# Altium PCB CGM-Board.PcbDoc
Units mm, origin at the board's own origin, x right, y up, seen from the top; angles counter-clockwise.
Board outline 25 x 32 mm, 4 copper layers (Top Layer, Signal Layer 2, Signal Layer 3, Bottom Layer), stack 1.6 mm thick; 78 components, 47 nets, 236 pads, 227 vias.
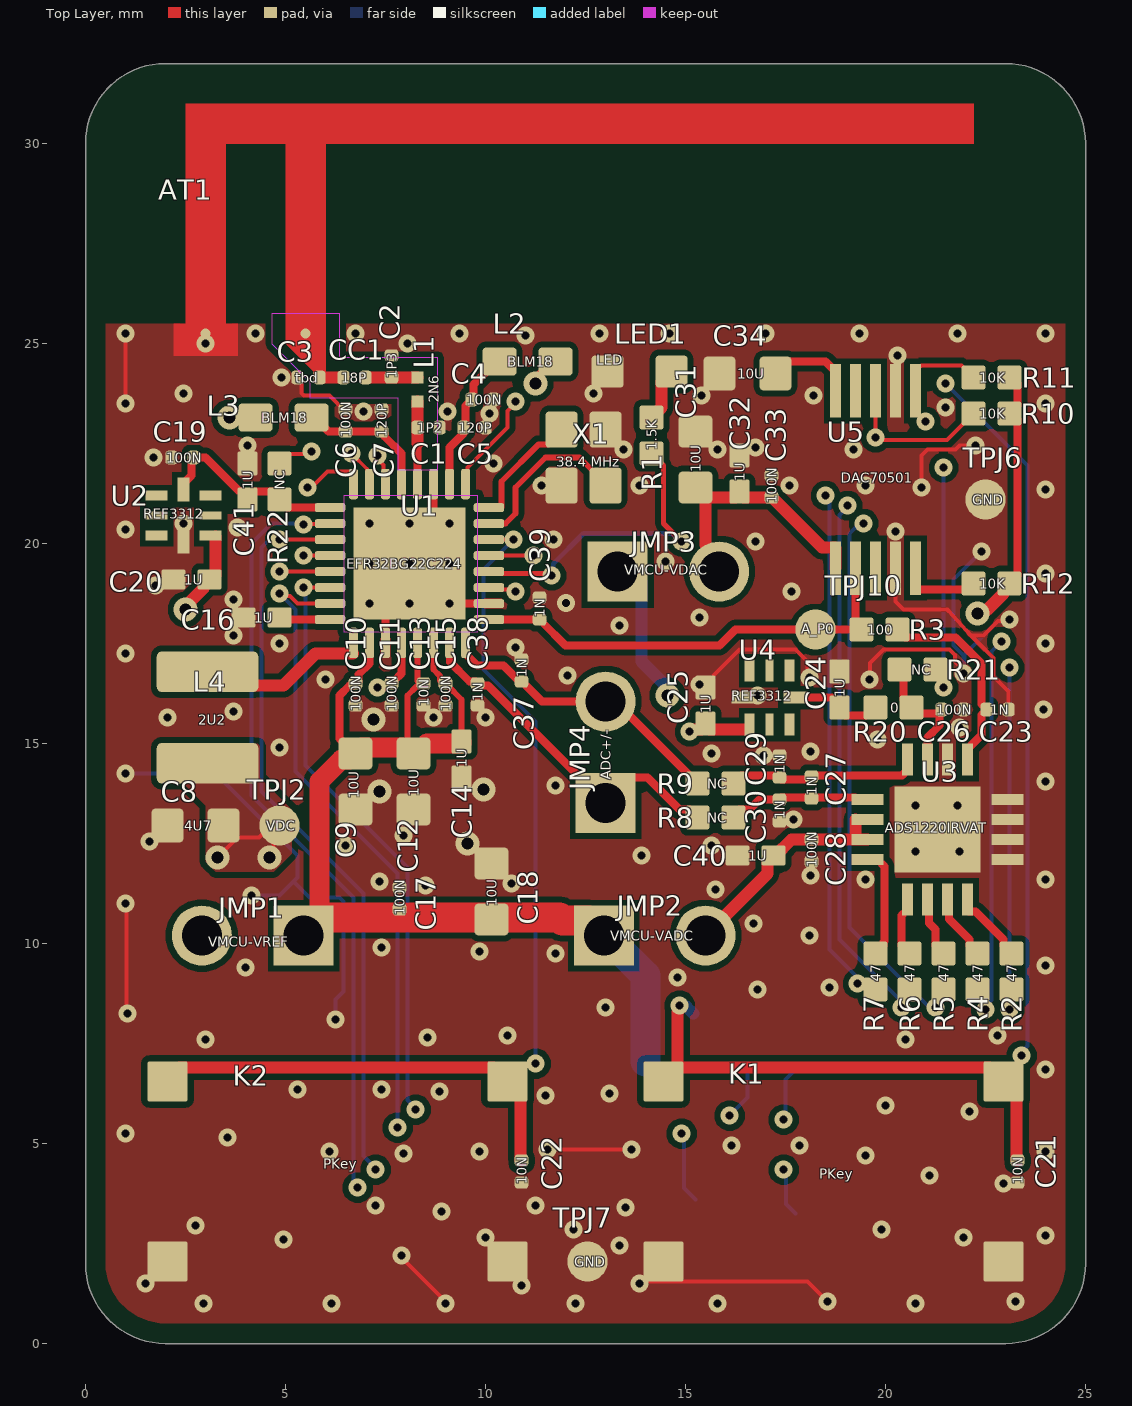
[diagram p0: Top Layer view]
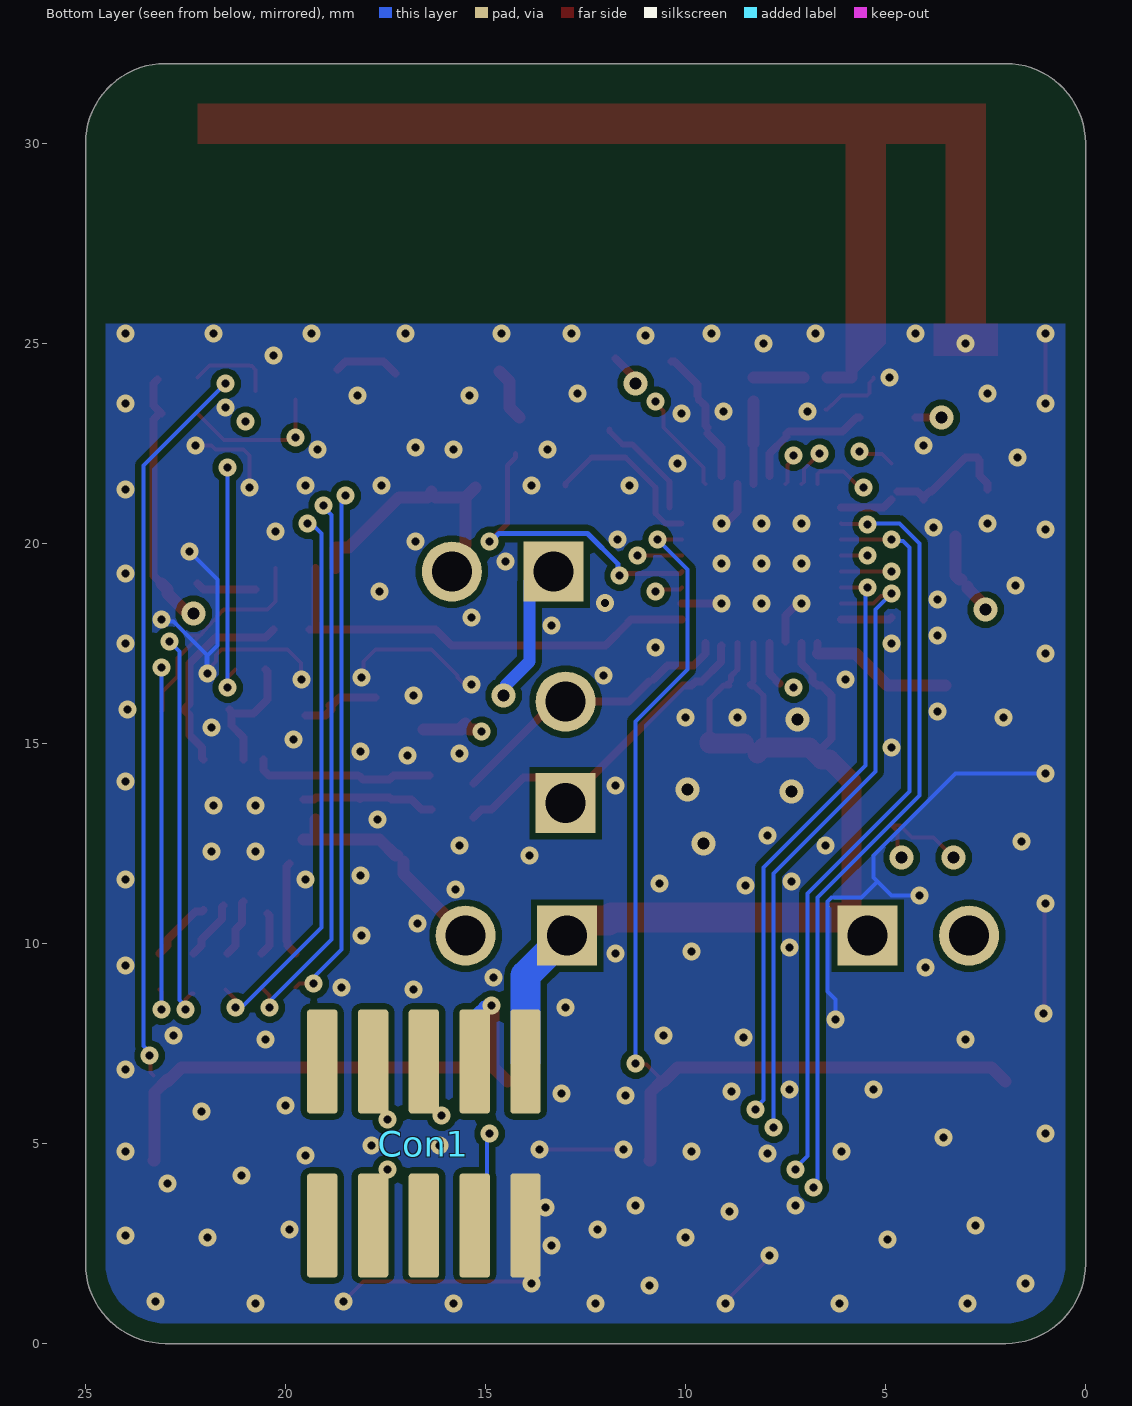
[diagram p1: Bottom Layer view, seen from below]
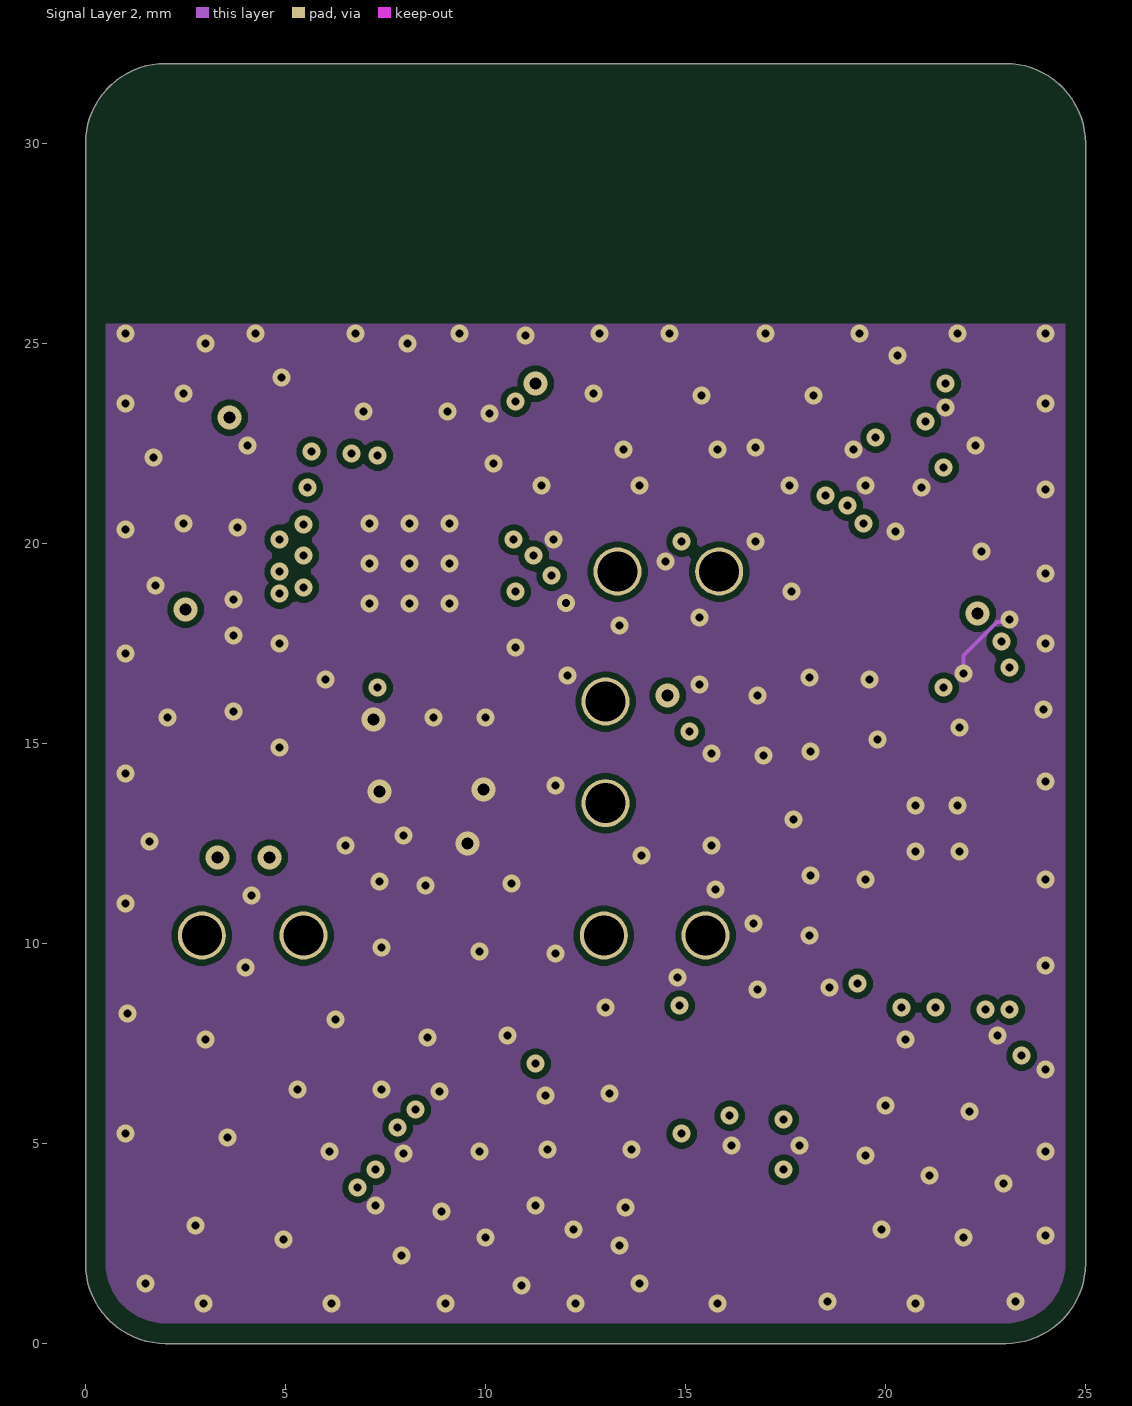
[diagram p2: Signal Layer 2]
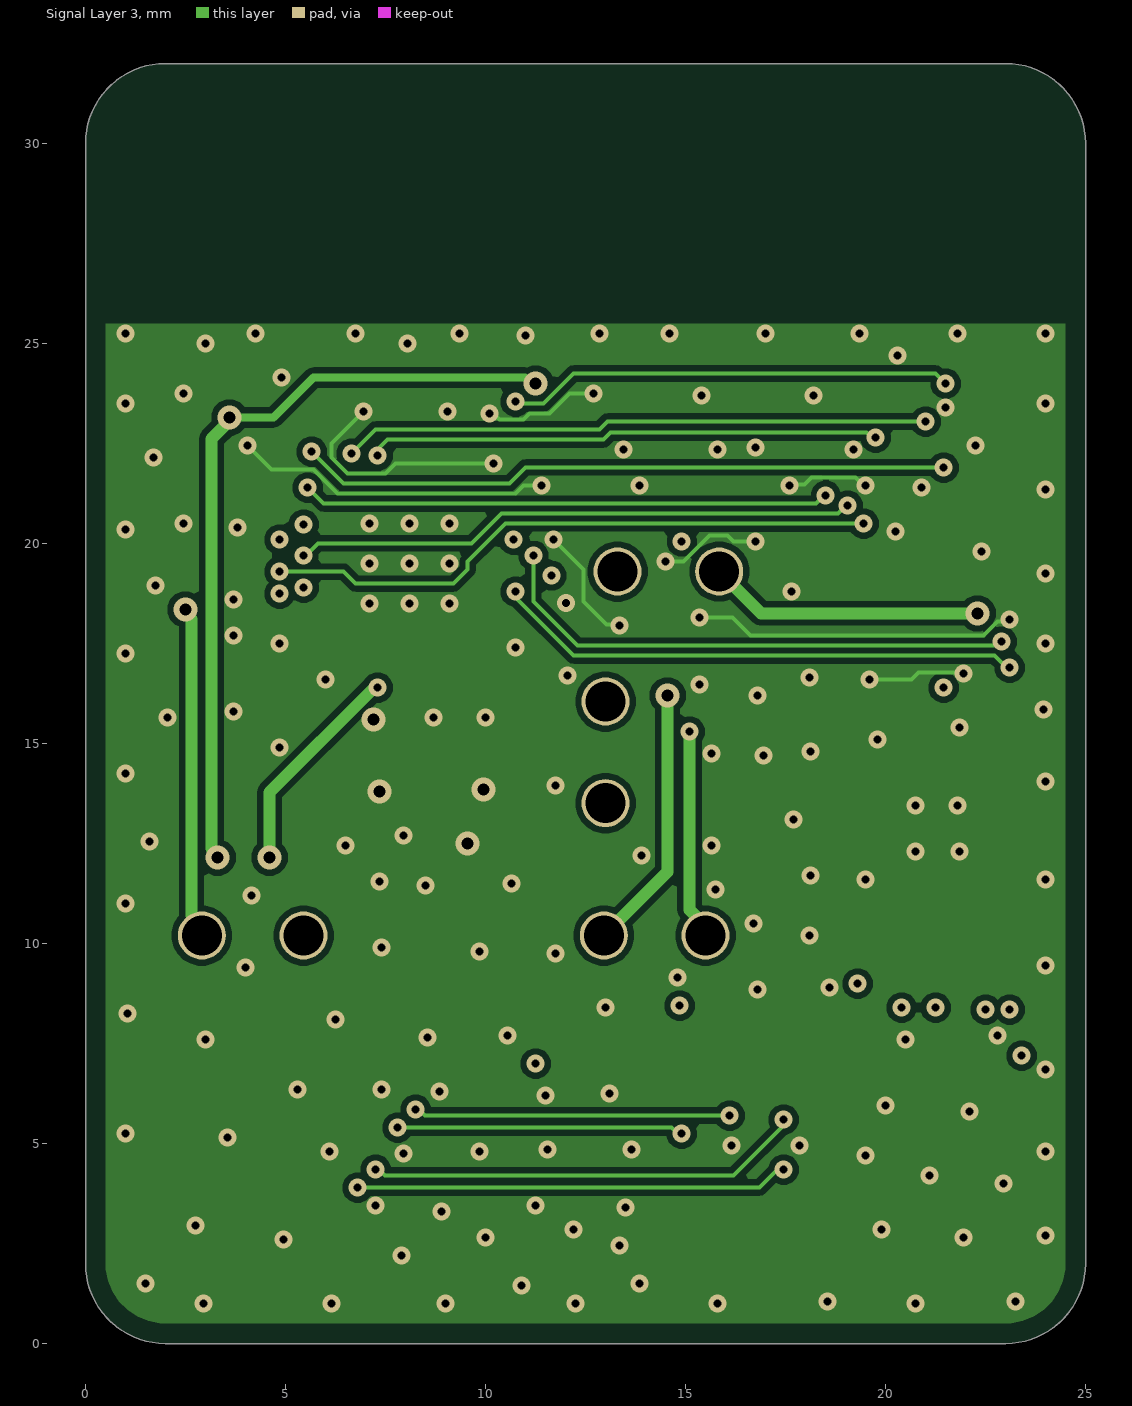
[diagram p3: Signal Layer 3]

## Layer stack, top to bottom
Top Solder: solder mask 0.0102, Solder Resist, Dk 3.5
Top Layer: signal copper 0.035
Dielectric 1: core 0.325, FR-4, Dk 4.2
Signal Layer 2: signal copper 0.018
Dielectric 3: prepreg 0.844, Dk 4.2
Signal Layer 3: signal copper 0.018
Dielectric 2: core 0.325, Dk 4.2
Bottom Layer: signal copper 0.035
Bottom Solder: solder mask 0.0102, Solder Resist, Dk 3.5

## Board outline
0,2 0,30 cw(c2,30) 2,32 23,32 cw(c23,30) 25,30 25,2 cw(c23,2) 23,0 2,0 cw(c2,2)

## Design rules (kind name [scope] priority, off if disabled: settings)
AcuteAngle [All] p1: minimum=7.00000000000000E+0001 checktracksonly=FALSE
BoardOutlineClearance [All] p1: gap=0.5 ignorepadtopadclearanceinfootprint=FALSE
Clearance Clearance_General [All] p1: gap=0.1 ignorepadtopadclearanceinfootprint=FALSE except(0.15: Arc-Poly Track-Poly SMDPad-Poly THPad-Poly Via-Poly Fill-Poly Poly-Poly Poly-Region Poly-Text Poly-Hole)
Clearance Clearance_RF [InNetClass('RF-Traces') vs InNet('GND')] p2: gap=0.5 ignorepadtopadclearanceinfootprint=FALSE
DiffPairsRouting [All] p1: maxlimit=0.254 minlimit=0.254 mostfreqgap=0.254 toplayer_minwidth=0.381 toplayer_maxwidth=0.381 toplayer_prefwidth=0.381 midlayer1_minwidth=0.381 midlayer1_maxwidth=0.381 midlayer1_prefwidth=0.381 midlayer2_minwidth=0.381 midlayer2_maxwidth=0.381 midlayer2_prefwidth=0.381 bottomlayer_minwidth=0.381 bottomlayer_maxwidth=0.381 bottomlayer_prefwidth=0.381 substack1={FA8A8519-551F-42C4-AF21-50C5882F2CE8} toplayer_{fa8a8519-551f-42c4-af21-50c5882f2ce8}_minwidth=0.381 toplayer_{fa8a8519-551f-42c4-af21-50c5882f2ce8}_maxwidth=0.381 toplayer_{fa8a8519-551f-42c4-af21-50c5882f2ce8}_prefwidth=0.381 midlayer1_{fa8a8519-551f-42c4-af21-50c5882f2ce8}_minwidth=0.381 midlayer1_{fa8a8519-551f-42c4-af21-50c5882f2ce8}_maxwidth=0.381 midlayer1_{fa8a8519-551f-42c4-af21-50c5882f2ce8}_prefwidth=0.381 midlayer2_{fa8a8519-551f-42c4-af21-50c5882f2ce8}_minwidth=0.381 midlayer2_{fa8a8519-551f-42c4-af21-50c5882f2ce8}_maxwidth=0.381 midlayer2_{fa8a8519-551f-42c4-af21-50c5882f2ce8}_prefwidth=0.381 bottomlayer_{fa8a8519-551f-42c4-af21-50c5882f2ce8}_minwidth=0.381 bottomlayer_{fa8a8519-551f-42c4-af21-50c5882f2ce8}_maxwidth=0.381 bottomlayer_{fa8a8519-551f-42c4-af21-50c5882f2ce8}_prefwidth=0.381 substack2={B08C36B3-7862-438E-B9FF-C3538867186E} toplayer_{b08c36b3-7862-438e-b9ff-c3538867186e}_minwidth=0.381 toplayer_{b08c36b3-7862-438e-b9ff-c3538867186e}_maxwidth=0.381 toplayer_{b08c36b3-7862-438e-b9ff-c3538867186e}_prefwidth=0.381 midlayer1_{b08c36b3-7862-438e-b9ff-c3538867186e}_minwidth=0.381 midlayer1_{b08c36b3-7862-438e-b9ff-c3538867186e}_maxwidth=0.381 midlayer1_{b08c36b3-7862-438e-b9ff-c3538867186e}_prefwidth=0.381 midlayer2_{b08c36b3-7862-438e-b9ff-c3538867186e}_minwidth=0.381 midlayer2_{b08c36b3-7862-438e-b9ff-c3538867186e}_maxwidth=0.381 midlayer2_{b08c36b3-7862-438e-b9ff-c3538867186e}_prefwidth=0.381 bottomlayer_{b08c36b3-7862-438e-b9ff-c3538867186e}_minwidth=0.381 bottomlayer_{b08c36b3-7862-438e-b9ff-c3538867186e}_maxwidth=0.381 bottomlayer_{b08c36b3-7862-438e-b9ff-c3538867186e}_prefwidth=0.381 substack3={B8B36AB3-2B2C-415E-8633-38694F6D9F5F} toplayer_{b8b36ab3-2b2c-415e-8633-38694f6d9f5f}_minwidth=0.381 toplayer_{b8b36ab3-2b2c-415e-8633-38694f6d9f5f}_maxwidth=0.381 toplayer_{b8b36ab3-2b2c-415e-8633-38694f6d9f5f}_prefwidth=0.381 midlayer1_{b8b36ab3-2b2c-415e-8633-38694f6d9f5f}_minwidth=0.381 midlayer1_{b8b36ab3-2b2c-415e-8633-38694f6d9f5f}_maxwidth=0.381 midlayer1_{b8b36ab3-2b2c-415e-8633-38694f6d9f5f}_prefwidth=0.381 midlayer2_{b8b36ab3-2b2c-415e-8633-38694f6d9f5f}_minwidth=0.381 midlayer2_{b8b36ab3-2b2c-415e-8633-38694f6d9f5f}_maxwidth=0.381 midlayer2_{b8b36ab3-2b2c-415e-8633-38694f6d9f5f}_prefwidth=0.381 bottomlayer_{b8b36ab3-2b2c-415e-8633-38694f6d9f5f}_minwidth=0.381 bottomlayer_{b8b36ab3-2b2c-415e-8633-38694f6d9f5f}_maxwidth=0.381 bottomlayer_{b8b36ab3-2b2c-415e-8633-38694f6d9f5f}_prefwidth=0.381 substack4={C90E24FC-0848-4387-93FF-582D14C2B24E} toplayer_{c90e24fc-0848-4387-93ff-582d14c2b24e}_minwidth=0.381 toplayer_{c90e24fc-0848-4387-93ff-582d14c2b24e}_maxwidth=0.381 toplayer_{c90e24fc-0848-4387-93ff-582d14c2b24e}_prefwidth=0.381 midlayer1_{c90e24fc-0848-4387-93ff-582d14c2b24e}_minwidth=0.381 midlayer1_{c90e24fc-0848-4387-93ff-582d14c2b24e}_maxwidth=0.381 midlayer1_{c90e24fc-0848-4387-93ff-582d14c2b24e}_prefwidth=0.381 midlayer2_{c90e24fc-0848-4387-93ff-582d14c2b24e}_minwidth=0.381 midlayer2_{c90e24fc-0848-4387-93ff-582d14c2b24e}_maxwidth=0.381 midlayer2_{c90e24fc-0848-4387-93ff-582d14c2b24e}_prefwidth=0.381 bottomlayer_{c90e24fc-0848-4387-93ff-582d14c2b24e}_minwidth=0.381 bottomlayer_{c90e24fc-0848-4387-93ff-582d14c2b24e}_maxwidth=0.381 bottomlayer_{c90e24fc-0848-4387-93ff-582d14c2b24e}_prefwidth=0.381 substack5={12135C53-A118-4A4B-B20C-ADFD1C1CED6B} toplayer_{12135c53-a118-4a4b-b20c-adfd1c1ced6b}_minwidth=0.381 toplayer_{12135c53-a118-4a4b-b20c-adfd1c1ced6b}_maxwidth=0.381 toplayer_{12135c53-a118-4a4b-b20c-adfd1c1ced6b}_prefwidth=0.381 midlayer1_{12135c53-a118-4a4b-b20c-adfd1c1ced6b}_minwidth=0.381 midlayer1_{12135c53-a118-4a4b-b20c-adfd1c1ced6b}_maxwidth=0.381 midlayer1_{12135c53-a118-4a4b-b20c-adfd1c1ced6b}_prefwidth=0.381 midlayer2_{12135c53-a118-4a4b-b20c-adfd1c1ced6b}_minwidth=0.381 midlayer2_{12135c53-a118-4a4b-b20c-adfd1c1ced6b}_maxwidth=0.381 midlayer2_{12135c53-a118-4a4b-b20c-adfd1c1ced6b}_prefwidth=0.381 bottomlayer_{12135c53-a118-4a4b-b20c-adfd1c1ced6b}_minwidth=0.381 bottomlayer_{12135c53-a118-4a4b-b20c-adfd1c1ced6b}_maxwidth=0.381 bottomlayer_{12135c53-a118-4a4b-b20c-adfd1c1ced6b}_prefwidth=0.381 maxuncoupledlength=12.7
HoleSize [All] p1: absolutevalues=TRUE maxlimit=5.08 minlimit=0.2 maxpercent=80.000 minpercent=20.000
HoleToHoleClearance HoleToHoleClearance_ANT1toPAD [Incomponent ('ANT1') vs ISpad] p1: gap=0 allowstackedmicrovias=TRUE
HoleToHoleClearance HoleToHoleClearance_U1toVIA_1 [InComponent ('U1') vs IsVia] p2: gap=0 allowstackedmicrovias=TRUE
HoleToHoleClearance [All] p3: gap=0.254 allowstackedmicrovias=TRUE
MinimumSolderMaskSliver [All] p1: minsoldermaskwidth=0.075
PasteMaskExpansion [All] p1: expansion=-0.05
PlaneConnect [All] p1: planeconnectstyle=Direct reliefexpansion=0.508 reliefentries=4 reliefconductorwidth=0.254 reliefairgap=0.254
PolygonConnect Polygon_VIA_Connect [IsVia] p1: connectstyle=Direct reliefconductorwidth=0.254 reliefentries=4 polygonreliefangle="90 Angle" airgapwidth=0.254
PolygonConnect [All] p2: connectstyle=Direct reliefconductorwidth=0.254 reliefentries=4 polygonreliefangle="90 Angle" airgapwidth=0.2
RoutingCorners [All] p1: cornerstyle=45-Degree minsetback=0.1 maxsetback=0.3
RoutingVias [All] p1: holewidth=0.2 width=0.45 viastyle="Through Hole" minholewidth=0.15 minwidth=0.4 maxholewidth=1 maxwidth=1.5
ShortCircuit ShortCircuit_ANTtoPAD [InNet('NetAT1_1') vs InNet('GND')] p1: allowed=TRUE
ShortCircuit [All] p2: allowed=FALSE
SilkToSilkClearance [All] p1: silktosilkclearance=0.1
SilkToSolderMaskClearance [IsPad] p1: minsilkscreentomaskgap=0.1 clearancetoexposedcopper=TRUE
SolderMaskExpansion [All] p1: expansion=0.05 istentingtop=FALSE
Width Width_Power [InNetClass('Power')] p1: maxlimit=0.5 minlimit=0.1 preferedwidth=0.2 substack1={FA8A8519-551F-42C4-AF21-50C5882F2CE8} substack2={B08C36B3-7862-438E-B9FF-C3538867186E} substack3={B8B36AB3-2B2C-415E-8633-38694F6D9F5F} substack4={C90E24FC-0848-4387-93FF-582D14C2B24E} substack5={12135C53-A118-4A4B-B20C-ADFD1C1CED6B}
Width Width_RF [InNetClass('RF-Traces')] p2: maxlimit=0.5 minlimit=0.1 preferedwidth=0.3 substack1={FA8A8519-551F-42C4-AF21-50C5882F2CE8} substack2={B08C36B3-7862-438E-B9FF-C3538867186E} substack3={B8B36AB3-2B2C-415E-8633-38694F6D9F5F} substack4={C90E24FC-0848-4387-93FF-582D14C2B24E} substack5={12135C53-A118-4A4B-B20C-ADFD1C1CED6B} checkconnectedcopper=TRUE
Width Width_RF1 [InNet('NetC1_1')] p3: maxlimit=0.5 minlimit=0.1 preferedwidth=0.2 substack1={FA8A8519-551F-42C4-AF21-50C5882F2CE8} substack2={B08C36B3-7862-438E-B9FF-C3538867186E} substack3={B8B36AB3-2B2C-415E-8633-38694F6D9F5F} substack4={C90E24FC-0848-4387-93FF-582D14C2B24E} substack5={12135C53-A118-4A4B-B20C-ADFD1C1CED6B}
Width [All] p4: maxlimit=5.08 minlimit=0.1 preferedwidth=0.1 substack1={FA8A8519-551F-42C4-AF21-50C5882F2CE8} substack2={B08C36B3-7862-438E-B9FF-C3538867186E} substack3={B8B36AB3-2B2C-415E-8633-38694F6D9F5F} substack4={C90E24FC-0848-4387-93FF-582D14C2B24E} substack5={12135C53-A118-4A4B-B20C-ADFD1C1CED6B} minimp=50.000000 maximp=50.000000 favimp=50.000000
20 further rules are at their usual default settings.

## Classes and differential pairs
component class "04_ DAC & ADC": C23 C24 C25 C26 C27 C28 C29 C30 C31 C32 C33 C34 C40 JMP1 JMP2 JMP3 JMP4 R2 R3 R4 R5 R6 R7 R8 R9 R10 R11 R12 R20 R21 TPJ2 TPJ6 TPJ7 TPJ10 U3 U4 U5
component class "03_ SoC GPIOs Connection": C17 C18 C19 C20 C21 C22 C37 C38 C39 C41 Con1 K1 K2 LED1 R1 R22 U1 U2
component class "02_ RF Match, Antenna & Power": AT1 C1 C2 C3 C4 C5 C6 C7 C8 C9 C10 C11 C12 C13 C14 C15 C16 CC1 L1 L2 L3 L4 X1

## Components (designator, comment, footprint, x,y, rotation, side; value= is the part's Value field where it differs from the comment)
AT1 "INVERTED_F" EM358x_INVERTED_F 2.5,25 r0 top locked net-tie
C1 "1P2" C0201_L 8.575,22.9 r0 top
C2 "1P3" C0201_L 7.65,24.425 r90 top
C3 "tbd" C0201_L 5.575,24.15 r180 top
C4 "100N" C0201_L 9.925,23.6 r0 top
C5 "120P" C0201_L 9.725,22.9 r0 top
C6 "100N" C0201_L 6.5,23.075 r90 top
C7 "120P" C0201_L 7.4,23.075 r90 top
C8 "4U7" C0603_L 2.75,12.95 r180 top
C9 "10U" C0603_L 6.75,14.05 r270 top
C10 "100N" C0201_L 6.75,16.225 r270 top
C11 "100N" C0201_L 7.65,16.225 r270 top
C12 "10U" C0603_L 8.2,14.05 r270 top
C13 "10N" C0201_L 8.45,16.225 r270 top
C14 "1U" C0402_L 9.4,14.6 r270 top
C15 "100N" C0201_L 9,16.225 r270 top
C16 "1U" C0402_L 4.4,18.15 r180 top
C17 "100N" C0201_L 7.85,11.125 r90 top
C18 "10U" C0603_L 10.15,11.3 r90 top
C19 "100N" C0201_L 2.425,22.15 r180 top
C20 "1U" C0402_L 2.65,19.1 r180 top
C21 "10N" C0201_L 23.3,4.3 r270 top locked
C22 "10N" C0201_L 10.9,4.3 r270 top locked
C23 "1N" C0201_L 22.8,15.85 r0 top locked
C24 "1U" C0402_L 18.85,16.35 r90 top
C25 "1U" C0402_L 15.5,15.95 r90 top
C26 "100N" C0201_L 21.675,15.85 r0 top
C27 "1N" C0201_L 18.15,13.9 r90 top
C28 "100N" C0201_L 18.15,12.325 r270 top
C29 "1N" C0201_L 17.35,14.425 r90 top
C30 "1N" C0201_L 17.35,13.325 r270 top
C31 "10U" C0603_L 15.25,22.1 r90 top
C32 "1U" C0402_L 16.35,21.75 r90 top
C33 "100N" C0201_L 17.15,21.425 r90 top
C34 "10U" C0603_L 16.55,24.25 r180 top
C37 "1N" C0201_L 10.9,16.825 r90 top
C38 "1N" C0201_L 9.8,16.225 r270 top
C39 "1N" C0201_L 11.35,18.375 r90 top
C40 "1U" C0402_L 16.75,12.2 r180 top
C41 "1U" C0402_L 4.05,21.55 r90 top
CC1 "18P" C0201_L 6.725,24.15 r180 top
Con1 "10Pin_Debug" 10Pin_Con 14,5 r270 bottom locked
JMP1 "VMCU-VREF" 2Pin-JMP 5.45,10.2 r180 top locked
JMP2 "VMCU-VADC" 2Pin-JMP 12.96,10.2 r0 top
JMP3 "VMCU-VDAC" 2Pin-JMP 13.3,19.3 r0 top locked
JMP4 "ADC+/-" 2Pin-JMP 13,13.51 r90 top
K1 "PKey" PKey-P 18.7,4.3 r0 top locked
K2 "PKey" PKey-P 6.3,4.3 r0 top locked
L1 "2N6" COIL_0201_L 8.3,23.85 r90 top
L2 "BLM18" COIL_MUR_BLM18_0603 11.05,24.55 r180 top
L3 "BLM18" COIL_MUR_BLM18_0603 4.95,23.15 r0 top
L4 "2U2" COIL_1008_L 3.05,15.65 r270 top
LED1 "LED" LED_Red 13.85,24.3 r0 top
R1 "1.5K" R0402_L 14.15,22.7 r90 top
R2 "47" R0402_L 23.15,9.3 r270 top
R3 "100" R0402_L 19.85,17.85 r180 top
R4 "47" R0402_L 22.3,9.3 r270 top
R5 "47" R0402_L 21.45,9.3 r270 top
R6 "47" R0402_L 20.6,9.3 r90 top
R7 "47" R0402_L 19.75,9.3 r90 top
R8 "NC" R0402_L 15.75,13.15 r180 top
R9 "NC" R0402_L 15.75,14 r180 top
R10 "10K" R0402_L 22.65,23.25 r180 top
R11 "10K" R0402_L 22.65,24.15 r180 top
R12 "10K" R0402_L 22.65,19 r180 top
R20 "0" R0402_L 20.2,15.9 r180 top
R21 "NC" R0402_L 20.8,16.85 r0 top locked
R22 "NC" R0402_L 4.85,21.55 r90 top
TPJ2 "VDC" TP_1.0_SMD 4.85,12.95 r90 top
TPJ6 "GND" TP_1.0_SMD 22.5,21.1 r90 top
TPJ7 "GND" TP_1.0_SMD 12.55,2.05 r90 top
TPJ10 "A_P0" TP_1.0_SMD 18.25,17.85 r90 top
U1 "EFR32BG22C224" QFN32_M040_4.0X4.0_EP_SL 8.1,19.5 r180 top
U2 "REF3312" RSE0008A 2.45,20.7 r0 top
U3 "ADS1220IRVAT" RVA16_2P14X2P14 21.3,12.85 r180 top locked
U4 "REF3312" RSE0008A 17.1,16.15 r270 top
U5 "DAC70501" DGS10_TEX 19.75,21.6 r90 top
X1 "38.4 MHz" KDS_DSX211SH_2016 12.45,22.15 r270 top

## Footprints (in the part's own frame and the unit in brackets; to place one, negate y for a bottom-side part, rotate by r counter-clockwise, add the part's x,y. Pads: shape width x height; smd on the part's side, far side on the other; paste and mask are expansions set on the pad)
2Pin-JMP [mm]
  rect 1.5x1.5 / inner round 1.2 / far side rect 1.5x1.5 hole 1: 1(0,0)
  round 1.5 / inner round 1.2 / far side round 1.5 hole 1: 2(2.54,0)
10Pin_Con [mm] "10-pin Debug Connector"
  rrect20% 2.6x0.76 smd: 1(-2.05,0) 2(2.05,0) 3(-2.05,-1.27) 4(2.05,-1.27) 5(-2.05,-2.54) 6(2.05,-2.54) 7(-2.05,-3.81) 8(2.05,-3.81) 9(-2.05,-5.08) 10(2.05,-5.08)
C0201_L [mm] "Capacitor, Chip; 0.60 mm L X 0.30 mm W X 0.33 mm H body"
  rrect52% 0.31x0.34 smd: 1(-0.275,0) 2(0.275,0)
  body extent -0.3,-0.15 0.3,0.15, height 0.3
C0402_L [mm] "Chip Capacitor, 2-Leads, Body 1.0x0.5mm, IPC High Density"
  rrect20% 0.6x0.5 smd mask+0.051: 1(-0.45,0) 2(0.45,0)
  body extent -0.5,-0.25 0.5,0.25, height 0.6
C0603_L [mm] "Capacitor, 0603, HiDens (190130)"
  rrect25% 0.8x0.85 smd: 1(-0.7,0) 2(0.7,0)
  body extent -0.88,-0.48 0.87,0.48, height 0.95
COIL_0201_L [mm] "JELF243C-0021"
  rrect10% 0.3x0.3 smd: 1(-0.3,0) 2(0.3,0)
  body extent -0.32,-0.17 0.32,0.17, height 0.33
COIL_1008_L [mil] "Chip Inductors, 1008 (2520), Coilcraft (190207)"
  rrect25% 40x100 smd: 1(-45,0) 2(45,0)
  body extent -58,-55 57,55, height 80
COIL_MUR_BLM18_0603 [mm] "COIL_MUR_BLM18P_0603"
  rrect25% 0.85x0.7 smd mask+0.051: 1(-0.7,0) 2(0.7,0)
  body extent -0.88,-0.48 0.87,0.48, height 0.95
DGS10_TEX [mil]
  rect 52.5x11 smd: 1(-87.25,39.37) 3(-87.25,0) 4(-87.25,-19.68) 5(-87.25,-39.37) 6(87.25,-39.37) 7(87.25,-19.68) 8(87.25,0) 10(87.25,39.37)
  rect 52.5x11 smd paste+0: 2(-87.25,19.69) 9(87.25,19.69)
  body extent -99,-61 99,61, height 43
EM358x_INVERTED_F [mm] "F-ANTENNA INVERSE 19.5 mm"
  round 0.254 smd paste-0.254 mask-0.254: 1(3,0.25) 2(0.5,0.25)
  Top Layer region: 0,6 19.7,6 19.7,5 3.5,5 3.5,0 2.5,0 2.5,5 1,5 1,0 0.5,0 0,0
KDS_DSX211SH_2016 [mm] "Copy of Silabs CE  X_KDS_DSX211SH_2.0X1.65-4"
  rrect20% 0.9x0.8 smd mask+0.051: 1(-0.7,-0.55) 2(0.7,-0.55) 3(0.7,0.55) 4(-0.7,0.55)
  body extent -1.07,-0.87 1.08,0.88, height 0.5
LED_Red [mm]
  rrect20% 0.8x0.8 smd: 1(-0.8,0) 2(0.8,0)
PKey-P [mm]
  rrect10% 1x1 smd: 1(-4.25,2.25) 2(-4.25,-2.25) 3(4.25,2.25) 4(4.25,-2.25)
QFN32_M040_4.0X4.0_EP_SL [mm]
  rrect50% 1.1x1.1 on Top Paste: 0(-0.65,0.65) 0(-0.65,-0.65) 0(0.65,0.65) 0(0.65,-0.65)
  rect 2.8x2.8 smd paste-10: 0(0,0)
  rrect50% 0.76x0.22 smd: 1(-1.985,1.4) 2(-1.985,1) 3(-1.985,0.6) 4(-1.985,0.2) 5(-1.985,-0.2) 6(-1.985,-0.6) 7(-1.985,-1) 8(-1.985,-1.4) 17(1.985,-1.4) 18(1.985,-1) 19(1.985,-0.6) 20(1.985,-0.2) 21(1.985,0.2) 22(1.985,0.6) 23(1.985,1) 24(1.985,1.4)
  rrect50% 0.22x0.76 smd: 9(-1.4,-1.985) 10(-1,-1.985) 11(-0.6,-1.985) 12(-0.2,-1.985) 13(0.2,-1.985) 14(0.6,-1.985) 15(1,-1.985) 16(1.4,-1.985) 25(1.4,1.985) 26(1,1.985) 27(0.6,1.985) 28(0.2,1.985) 29(-0.2,1.985) 30(-0.6,1.985) 31(-1,1.985) 32(-1.4,1.985)
  body extent -2,-2 2,2, height 0.56
R0402_L [mm] "Chip Resistor, 2-Leads, Body 1.0x0.5mm, IPC High Density"
  rrect20% 0.6x0.6 smd mask+0.051: 1(-0.45,0) 2(0.45,0)
  body extent -0.5,-0.25 0.5,0.25, height 0.6
RSE0008A [mm] "UQFN-8PIN"
  rect 0.55x0.25 smd paste+0 mask+0.051: 1(-0.675,0.5) 3(-0.675,-0.5) 5(0.675,-0.5) 7(0.675,0.5)
  rect 0.55x0.2 smd paste+0 mask+0.051: 2(-0.675,0) 6(0.675,0)
  rect 0.3x0.6 smd paste+0 mask+0.051: 4(0,-0.65) 8(0,0.65)
  body extent -0.13,-0.13 0.13,0.13, height 0.25
RVA16_2P14X2P14 [mm]
  rect 0.8x0.28 smd: 1(-1.75,0.75) 2(-1.75,0.25) 3(-1.75,-0.25) 4(-1.75,-0.75) 9(1.75,-0.75) 10(1.75,-0.25) 11(1.75,0.25) 12(1.75,0.75)
  rect 0.28x0.8 smd: 5(-0.75,-1.75) 6(-0.25,-1.75) 7(0.25,-1.75) 8(0.75,-1.75) 13(0.75,1.75) 14(0.25,1.75) 15(-0.25,1.75) 16(-0.75,1.75)
  rect 2.14x2.14 smd: 17(0,0)
  body extent -1.85,-1.85 1.85,1.85, height 1.4
TP_1.0_SMD [mm] "Test Point, 1.0 mm, SMD"
  round 1 smd paste-0.501: 1(0,0)
  body extent -0.2,-0.2 0.2,0.2, height 0.01

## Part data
C1: library part C0201, Tolerance=±0.05P
C2 C3: library part C0201, Tolerance=±0.1P
C4 C6 C10 C11 C15 C17 C19 C20 C21 C22 C24 C25 C26 C28 C32 C33 C40 C41: library part C0201, Rating=25V, Tolerance=10%
C5 C7: library part C0201, Rating=50V, Tolerance=5%
C8: library part C0603, Rating=6.3V, Tolerance=20%
C9 C12 C18 C31 C34: library part C0603, Rating=25V, Tolerance=20%
C13 C23 C27 C29 C30 C37 C38 C39: library part C0201, Rating=10V, Tolerance=10%
C14 C16: library part C0402, Rating=25V, Tolerance=10%
CC1: library part C0201, Tolerance=±2%
JMP1 JMP2 JMP3 JMP4: library part JMP-2P
L1: library part L0201, Tolerance=±0.1N
L2 L3: library part BLM21B102S
L4: library part L1008, Tolerance=+/-20%
LED1: library part LED_P
R1 R2 R3 R4 R5 R6 R7 R8 R9 R10 R11 R12 R20 R21 R22: library part RESISTOR, Tolerance=5%
TPJ2 TPJ6 TPJ7 TPJ10: library part TPJ_SMD_Dup1
U1: library part EFR32xG22_QFN32_2G4
U2 U4: library part REF3312AIRSET, "No Description Available", PartNumber=REF3312AIRSER
U3: "No Description Available"
U5: library part DAC70501MDGST, "No Description Available"
X1: library part DSX211SH

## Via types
v1: diameter 0.45/0.45/0.45/0.45 (per signal layer), hole 0.2, Top Layer to Bottom Layer, tented both sides, 215 vias
v2: diameter 0.6, hole 0.3, Top Layer to Bottom Layer, tented both sides, 11 vias
v3: diameter 0.45, hole 0.2, Top Layer to Bottom Layer, tented both sides, 1 vias

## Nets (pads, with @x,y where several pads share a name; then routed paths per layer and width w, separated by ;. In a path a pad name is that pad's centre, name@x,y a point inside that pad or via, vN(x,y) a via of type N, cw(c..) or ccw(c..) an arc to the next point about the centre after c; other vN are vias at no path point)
ADC_N1: C37.1 JMP4.2 R9.2 U1.32 | length 7.1
  Top Layer w0.2: U1.32 9.5,17.245 9.795,16.95 10.45,16.95 C37.1@10.8,16.6 ; C37.1@10.915,16.55 11.415,16.05 JMP4.2 ; JMP4.2@13.2,16 13.3,16 R9.2
ADC_P0: C39.1 R3.2 TPJ10.1 U1.1 U5.2 | length 11.2
  Top Layer w0.2: U1.1 C39.1 11.365,18.1 11.42,18.045 11.42,18.03 12,17.45 15.85,17.45 16.25,17.85 TPJ10.1 19.2,17.85 R3.2 ; R3.2@19.2,17.95 19.25,18 U5.2
ADC_P1: C38.1 JMP4.1 R8.2 U1.31 | length 8
  Top Layer w0.2: U1.31@9.1,17.45 9.11,17.44 9.11,17.04 9.595,16.555 9.745,16.555 C38.1 9.85,16.45 10.06,16.45 JMP4.1 ; JMP4.1@13.5,14.15 14.05,14.15 14.85,13.35 14.95,13.35 15.1,13.35 R8.2
ADC_Vref: C24.1 R20.2 U4.8 | length 2
  Top Layer w0.2: U4.8 18.65,16.15 18.85,15.95 C24.1@18.9,15.95 ; C24.1 18.85,15.85 19,15.7 19.05,15.7 R20.2@19.5,15.7
BTN_EM4: C22.1 K2.1 K2.3 U1.6 | length 26.3
  Top Layer w0.1: U1.6 v1(10.7,20.1) ; K2.3@10.65,6.65 10.975,6.975 11.225,6.975 v1(11.25,7)
  Top Layer w0.3: K2.1@2,6.55 2.35,6.9 10.2,6.9 K2.3 ; K2.3@10.6,6.55 10.88,6.27 10.88,4.58 10.885,4.575 C22.1
  Bottom Layer w0.1: v1(10.7,20.1) 9.95,19.35 9.95,16.85 11.25,15.55 v1(11.25,7)
DAC_Vref: C34.1 U5.10 | length 1.7
  Top Layer w0.2: C34.1 17.55,24.55 18.5,24.55 U5.10@18.7,24.35
EFR32_#RESET: C21.1 Con1.3 K1.1 K1.3 U1.9 | length 45
  Top Layer w0.1: U1.9 9.552,21.537 9.552,21.902 10.55,22.9 10.55,23.316 10.75,23.516 v1(10.75,23.55) ; K1.3@23.3,6.7 23.375,6.775 23.375,7.175 v1(23.4,7.2)
  Top Layer w0.3: K1.1 K1.1@14.8,6.9 ; v1(14.85,8.45) 14.821,8.421 14.821,8.315 14.8,8.294 K1.1@14.8,6.9 ; K1.3 22.6,6.9 K1.1@14.8,6.9 ; K1.3@22.95,6.6 23.28,6.27 23.28,4.58 23.285,4.575 C21.1
  Signal Layer 3 w0.1: v1(10.75,23.55) 10.8,23.5 11.45,23.5 12.2,24.25 21.25,24.25 v1(21.5,24)
  Bottom Layer w0.1: v1(21.5,24) 23.55,21.95 23.55,7.434 23.4,7.284 v1(23.4,7.2)
  Bottom Layer w0.3: v1(14.85,8.45) 14.879,8.421 15.019,8.421 15.191,8.25 Con1.3@15.2,8.25
GND: AT1.2 C1.2 C2.2 C3.2 C4.2 C5.2 C6.2 C7.2 C8.2 C9.2 C10.2 C11.2 C12.2 C13.2 C14.2 C15.2 C16.2 C17.2 C18.2 C19.2 C20.2 C21.2 C22.2 C23.2 C24.2 C25.2 C26.2 C28.2 C29.2 C30.2 C31.2 C32.2 C33.2 C34.2 C37.2 C38.2 C39.2 C40.2 C41.2 Con1.2 K1.2 K1.4 K2.2 K2.4 LED1.1 TPJ6.1 TPJ7.1 U1.0@8.1,19.5 U1.2 U1.11 U1.27 U2.4 U3.1 U3.2 U3.3 U3.4 U3.6 U3.17 U4.4 U5.4 U5.7 X1.2 X1.4 | length 88.1
  Top Layer w0.1: v1(1,11) 1.025,10.975 1.025,8.275 v1(1.05,8.25) ; v1(1,23.5) v1(1,25.25) ; C3.2 5.3,24.118 5.4,24.018 5.4,23.759 5.459,23.7 6.1,23.7 6.345,23.455 6.363,23.455 6.468,23.35 C6.2 ; v1(7.9,2.2) 7.9,2.15 9,1.05 v1(9,1) ; v1(11.55,4.85) v1(13.65,4.85) ; v1(13.85,1.5) 13.9,1.55 18.05,1.55 v1(18.55,1.05) ; C25.2@15.35,16.5 C25.2@15.55,16.5 ; C25.2 15.5,16.5 C25.2@15.55,16.5 ; v1(18.1,16.65) 18.05,16.7 18.05,17.05 17.75,17.35 16.35,17.35 15.7,16.7 15.7,16.65 C25.2@15.55,16.5 ; v1(19.6,16.6) 19.615,16.615 19.615,17.015 19.95,17.35 21.6,17.35 21.742,17.208 21.742,17.053 21.95,16.845 v1(21.95,16.75) ; U5.4 20.25,18.55 20.45,18.35 21.543,18.35 21.573,18.321 21.575,18.319 22.022,17.82 ; v1(20.9,21.4) 20.9,22.2 21.05,22.35 21.75,22.35 21.85,22.45 v1(22.25,22.45) ; C23.2@23.1,15.8 23.075,15.825 C23.2 23.075,16.303 22.7,16.678 22.7,17.142 22.142,17.7 ; v1(23.1,18.1) 23.06,18.06 22.81,18.06 22.45,17.7 22.142,17.7 ; 22.022,17.82 22.101,17.731 22.103,17.729 22.132,17.7 22.142,17.7 ; 22.022,17.82 22.142,17.7
  Top Layer w0.2: v1(7.1,18.5) 7.2,18.5 7.5,18.2 U1.27@7.5,17.55 ; U1.11 8.7,20.85 8.7,20.8 9,20.5 v3(9.1,20.5) ; v1(9.1,18.5) U1.2 U1.2@10.1,18.5
  Signal Layer 2 w0.1: v1(21.95,16.75) 21.95,17.2 22.783,18.033 23.033,18.033 v1(23.1,18.1)
  Signal Layer 3 w0.1: v1@4.05,22.4 4.1,22.4 4.65,21.85 5.7,21.85 6.3,21.25 10.75,21.25 10.95,21.45 v1(11.4,21.45) ; v1(6.95,23.3) 6.15,22.5 6.15,22.15 6.55,21.75 7.5,21.75 7.75,22 v1(10.2,22) ; v1(10.1,23.25) 10.195,23.25 10.345,23.1 10.95,23.1 11.1,23.25 11.6,23.25 12.1,23.75 v1(12.7,23.75) ; v1(11.7,20.1) 12.45,19.35 12.45,18.55 13.025,17.975 13.325,17.975 v1(13.35,17.95) ; v1(14.5,19.55) 14.95,19.55 15.6,20.2 16.05,20.2 16.2,20.05 v1(16.75,20.05) ; v1(15.35,18.15) 16.18,18.15 16.63,17.7 22.45,17.7 22.8,18.05 23.05,18.05 v1(23.1,18.1) ; v1(17.6,21.45) 17.625,21.475 17.975,21.475 18.15,21.65 19.25,21.65 19.45,21.45 v1(19.5,21.45) ; v1(19.6,16.6) 20.654,16.6 20.829,16.775 21.925,16.775 v1(21.95,16.75)
  Bottom Layer w0.1: v1(1,14.25) 3.25,14.25 5.3,12.2 5.3,11.65 5.2,11.55 ; v1(4.15,11.2) 4.85,11.2 5.2,11.55 ; v1(6.25,8.1) 6.25,8.6 6.45,8.8 6.45,11.05 6.35,11.15 5.6,11.15 5.2,11.55 ; v1(22.4,19.8) 21.7,19.1 21.7,17.45 21.95,17.2 ; v1(23.1,18.1) 23.05,18.05 22.8,18.05 21.95,17.2 ; 21.95,17.2 v1(21.95,16.75) 21.975,16.775 21.975,17.175 21.95,17.2
  other v1: 2.95,1 6.15,1 12.25,1 15.8,1 20.75,1 23.25,1.05 10.9,1.45 1.5,1.5 13.35,2.45 4.95,2.6 10,2.65 21.95,2.65 24,2.7 12.2,2.85 19.9,2.85 2.75,2.95 8.9,3.3 13.5,3.4 7.25,3.45 11.25,3.45 22.95,4 21.1,4.2 19.5,4.7 7.95,4.75 6.1,4.8 9.85,4.8 24,4.8 16.15,4.95 17.85,4.95 3.55,5.15 1,5.25 22.1,5.8 20,5.95 11.5,6.2 13.1,6.25 8.85,6.3 5.3,6.35 7.4,6.35 24,6.85 3,7.6 20.5,7.6 8.55,7.65 10.55,7.7 22.8,7.7 13,8.4 16.8,8.85 18.6,8.9 14.8,9.15 4,9.4 24,9.45 11.75,9.75 9.85,9.8 7.4,9.9 18.1,10.2 16.7,10.5 15.75,11.35 8.5,11.45 10.65,11.5 7.35,11.55 19.5,11.6 24,11.6 18.125,11.7 13.9,12.2 20.75,12.3 21.85,12.3 6.5,12.45 15.65,12.45 1.6,12.55 7.95,12.7 17.7,13.1 20.75,13.45 21.8,13.45 11.75,13.95 24,14.05 16.95,14.7 15.65,14.75 18.125,14.8 4.85,14.9 19.8,15.1 21.85,15.4 2.05,15.65 8.7,15.65 10,15.65 3.7,15.8 23.95,15.85 16.8,16.2 15.35,16.475 6,16.6 12.05,16.7 1,17.25 10.75,17.4 4.85,17.5 24,17.5 3.7,17.7 8.1,18.5 12.015,18.515 3.7,18.6 17.65,18.8 1.75,18.95 24,19.25 7.1,19.5 8.1,19.5 9.1,19.5 20.25,20.3 1,20.35 3.8,20.4 2.45,20.5 7.1,20.5 8.1,20.5 24,21.35 13.85,21.45 1.7,22.15 13.45,22.35 15.8,22.35 19.2,22.35 16.75,22.4 4.05,22.45 9.05,23.3 21.5,23.4 24,23.5 15.4,23.7 18.2,23.7 2.45,23.75 4.9,24.15 20.3,24.7 3,25 8.05,25 11,25.2 4.25,25.25 6.75,25.25 9.35,25.25 12.85,25.25 14.6,25.25 17,25.25 19.35,25.25 21.8,25.25 24,25.25
  other v2: 9.55,12.5 7.35,13.8 9.95,13.85 7.2,15.6
ISR: R7.1 U1.16 | length 27.8
  Top Layer w0.1: v1(5.55,21.4) 5.645,21.4 6.045,21.8 6.64,21.8 6.7,21.74 U1.16 ; v1(19.3,9) 19.65,9 R7.1@19.75,8.9
  Signal Layer 3 w0.1: v1(5.55,21.4) 5.95,21 18.266,21 18.466,21.2 v1(18.5,21.2)
  Bottom Layer w0.1: v1(18.5,21.2) 18.5,21.105 18.6,21.005 18.6,9.85 19.233,9.217 19.233,9.067 v1(19.3,9)
LED_EN: R1.1 U1.4 | length 8
  Top Layer w0.12: U1.4 10.135,19.25 11.6,19.25 v1(11.65,19.2) ; R1.1@14.25,22.25 14.25,22.15 14.45,21.95 14.45,20.5 v1(14.9,20.05)
  Bottom Layer w0.12: v1(11.65,19.2) 11.691,19.241 11.691,19.491 12.45,20.25 14.665,20.25 14.865,20.05 v1(14.9,20.05)
NetAT1_1: AT1.1 C3.1 CC1.2 | length 1.2
  Top Layer w0.3: 5.85,24.75 C3.1 CC1.2
NetC1_1: C1.1 L1.1 U1.12 | length 2.1
  Top Layer w0.2: U1.12 8.3,22.5
  Top Layer w0.3: 8.3,22.5 C1.1 L1.1
NetC2_1: C2.1 CC1.1 L1.2 | length 1.2
  Top Layer w0.3: CC1.1@7.05,24.15 C2.1 L1.2
NetC4_1: C4.1 C5.1 L2.2 U1.10 | length 3.2
  Top Layer w0.2: U1.10@9.1,21.685 9.1,22.4 C5.1@9.45,22.75 ; C5.1 9.5,22.95 9.5,23.435 C4.1@9.657,23.593 ; C4.1@9.7,23.7 9.7,23.975 10.275,24.55 L2.2
NetC6_1: C6.1 C7.1 L3.2 U1.13 | length 3.2
  Top Layer w0.2: L3.2 5.725,23.15 6.075,22.8 C6.1 C7.1 7.415,22.8 7.47,22.745 7.47,22.68 7.9,22.25 U1.13@7.9,21.685
NetC16_1: C16.1 U1.24 | length 1.3
  Top Layer w0.2: C16.1 4.9,18.1 U1.24
NetC23_1: C23.1 R3.1 U3.5 | length 5.1
  Top Layer w0.2: R3.1 20.5,17.65 21.75,17.65 22.4,17 22.4,15.99 22.5,15.89 C23.1@22.5,15.85 ; U3.5 22.09,14.64 22.09,14.9 22.4,15.21 22.4,15.71 22.525,15.835 C23.1
NetC26_1: C26.1 R20.1 R21.1 U3.7 | length 3.2
  Top Layer w0.2: R21.1@20.5,16.85 20.45,16.8 20.45,16.1 R20.1 20.8,15.75 21.3,15.75 21.33,15.78 C26.1@21.345,15.78 ; U3.7 21.05,15.15 21.345,15.445 C26.1@21.345,15.78 ; C26.1 21.345,15.795 C26.1@21.345,15.78
NetC27_1: C27.1 C30.1 R8.1 U3.9 | length 3.4
  Top Layer w0.2: R8.1@16.35,13.35 16.6,13.35 16.85,13.6 C30.1 17.4,13.65 18.125,13.65 C27.1 ; C27.1@18.137,13.613 18.175,13.65 19.24,13.65 19.29,13.6 U3.9
NetC27_2: C27.2 C29.1 R9.1 U3.8 | length 4.5
  Top Layer w0.2: R9.1@16.4,14.2 17.3,14.2 C29.1 17.4,14.1 18.06,14.1 18.135,14.175 C27.2 ; C27.2@18.19,14.2 20.41,14.2 20.55,14.34 U3.8
NetL4_1: L4.1 U1.25 | length 3.8
  Top Layer w0.2: U1.25@6.69,17.25 6.7,17.26 U1.25
  Top Layer w0.3: L4.1@3.5,16.45 4.95,16.45 5.75,17.25 U1.25@6.69,17.25
NetLED1_2: LED1.2 R1.2 | length 1.4
  Top Layer w0.3: R1.2 14.4,23.4 14.4,24.05 LED1.2
NetR2_1: R2.1 U3.16 | length 1.6
  Top Layer w0.2: U3.16@22.05,10.84 22.09,10.8 22.25,10.8 22.95,10.1 22.95,9.95 R2.1
NetR4_1: R4.1 U3.15 | length 1.5
  Top Layer w0.2: U3.15@21.55,10.95 21.59,10.91 21.59,10.61 22.1,10.1 22.1,9.95 R4.1
NetR5_1: R5.1 U3.14 | length 1.5
  Top Layer w0.2: U3.14@21.05,11.05 21.09,11.01 21.09,10.51 21.25,10.35 21.25,9.95 R5.1
NetR6_2: R6.2 U3.13 | length 1.1
  Top Layer w0.2: U3.13@20.45,10.75 20.4,10.7 20.4,9.95 R6.2
NetR7_2: R7.2 U3.12 | length 2.4
  Top Layer w0.2: R7.2 19.95,9.95 19.95,10.042 19.975,10.067 19.975,11.925 U3.12@19.9,12
NetR12_2: R12.2 U5.5 | length 1.5
  Top Layer w0.2: U5.5@20.75,18.85 22.05,18.85 R12.2
NetU1_7: U1.7 X1.3 | length 4.3
  Top Layer w0.15: U1.7@10.1,20.5 10.5,20.5 10.75,20.75 10.75,21.4 11.5,22.15 12.35,22.15 13,21.5 X1.3
NetU1_8: U1.8 X1.1 | length 2.7
  Top Layer w0.15: U1.8@10.4,20.9 10.4,21.55 11.328,22.478 11.575,22.478 11.9,22.803 X1.1
SCL: R11.2 U1.15 U5.6 | length 17.8
  Top Layer w0.1: v1(6.65,22.25) 7.043,21.857 7.043,21.542 U1.15 ; U5.6 20.75,24.343 20.84,24.433 20.881,24.433 20.898,24.45 21.895,24.45 22.195,24.15 R11.2
  Signal Layer 3 w0.1: v1(6.65,22.25) 7.25,22.85 12.85,22.85 13.05,23.05 v1(21,23.05)
SDA: R10.2 U1.14 U5.8 | length 17.3
  Top Layer w0.1: v1(7.3,22.2) 7.3,22.116 7.45,21.966 7.45,21.535 U1.14 ; U5.8@19.75,23.6 v1(19.75,22.65) 19.813,22.587 21.537,22.587 R10.2
  Signal Layer 3 w0.1: v1(7.3,22.2) 7.367,22.267 7.367,22.417 7.55,22.6 12.95,22.6 13.125,22.775 19.53,22.775 19.655,22.65 v1(19.75,22.65)
SoC_Vref: C19.1 C41.1 R22.1 U1.17 U2.8 | length 4.8
  Top Layer w0.2: U2.8 2.45,21.5 2.65,21.7 2.65,22.08 2.67,22.1 C19.1@2.7,22.1 ; C19.1 C19.1 3.001,22.149 3.85,21.3 3.9,21.3 C41.1@4.05,21.15 ; R22.1@4.7,21.3 4.2,21.3 C41.1@4.05,21.15 ; R22.1 5.05,20.9 U1.17 ; C41.1@4.05,21.15 C41.1 C41.1@4.05,21.15
SPI_CLK: R4.2 U1.5 | length 24.3
  Top Layer w0.1: U1.5 v1(11.2,19.7) ; R4.2@22.3,8.75 22.346,8.75 22.495,8.601 22.495,8.355 v1(22.5,8.35)
  Signal Layer 3 w0.1: v1(11.2,19.7) 11.2,18.55 12.3,17.45 22.705,17.45 22.805,17.55 v1(22.9,17.55)
  Bottom Layer w0.1: v1(22.5,8.35) 22.5,8.434 22.65,8.584 22.65,17.3 v1(22.9,17.55)
SPI_CS: R2.2 U1.3 | length 23
  Top Layer w0.1: U1.3 10.135,18.85 10.7,18.85 v1(10.75,18.8) ; v1(23.1,8.35) 23.1,8.8 R2.2
  Signal Layer 3 w0.1: v1(10.75,18.8) 10.817,18.733 10.817,18.583 12.2,17.2 22.72,17.2 23.02,16.9 v1(23.1,16.9)
  Bottom Layer w0.1: v1(23.1,8.35) v1(23.1,16.9)
SPI_MISO: R6.1 U1.20 | length 28.6
  Top Layer w0.1: v1(5.45,19.7) U1.20 ; v1(20.4,8.4) 20.405,8.405 20.405,8.705 R6.1@20.6,8.9
  Signal Layer 3 w0.1: v1(5.45,19.7) 5.509,19.7 5.809,20 9.65,20 10.4,20.75 18.816,20.75 19.016,20.95 v1(19.05,20.95)
  Bottom Layer w0.1: v1(19.05,20.95) 19.05,20.916 18.85,20.716 18.85,10.1 20.333,8.617 20.333,8.467 v1(20.4,8.4)
SPI_MOSI: R5.2 U1.21 | length 30.6
  Top Layer w0.1: v1(4.85,19.3) U1.21 ; v1(21.25,8.4) 21.255,8.405 21.255,8.605 R5.2@21.5,8.85
  Signal Layer 3 w0.1: v1(4.85,19.3) 6.45,19.3 6.75,19 9.2,19 9.55,19.35 9.55,19.55 10.5,20.5 v1(19.45,20.5)
  Bottom Layer w0.1: v1(19.45,20.5) 19.355,20.5 19.24,20.385 19.235,20.385 19.1,20.25 19.1,10.4 21.033,8.467 21.183,8.467 v1(21.25,8.4)
SWCLK: Con1.8 U1.18 | length 31.5
  Top Layer w0.1: v1(5.45,20.475) 5.462,20.487 6.102,20.487 U1.18
  Signal Layer 3 w0.1: v1(6.8,3.9) 16.85,3.9 17.233,4.283 17.383,4.283 v1(17.45,4.35)
  Bottom Layer w0.1: v1(5.45,20.475) 5.425,20.5 4.65,20.5 4.15,20 4.15,13.7 6.7,11.15 6.7,4.095 6.8,3.995 v1(6.8,3.9) ; v1(17.45,4.35) 17.45,4.255 17.517,4.188 17.517,3.483 Con1.8@17.75,3.25
SWDIO: Con1.7 U1.19 | length 30.9
  Top Layer w0.1: v1(4.85,20.1) U1.19
  Signal Layer 3 w0.1: v1(7.25,4.35) 7.334,4.35 7.484,4.2 16.2,4.2 17.383,5.383 17.383,5.533 v1(17.45,5.6)
  Bottom Layer w0.1: v1(4.85,20.1) 4.81,20.06 4.56,20.06 4.4,19.9 4.4,13.8 6.95,11.25 6.95,4.684 7.25,4.384 v1(7.25,4.35) ; v1(17.45,5.6) 17.503,5.653 17.503,6.603 Con1.7@17.8,6.9
VADC: C25.1 C28.1 C40.1 JMP2.2 U3.10 U3.11 U4.5 | length 12.4
  Top Layer w0.3: v1(15.1,15.3) 15.141,15.3 15.191,15.35 15.4,15.35 C25.1@15.5,15.45 ; JMP2.2 17.05,11.75 C40.1@17.05,12.05 ; C25.1 15.6,15.4 15.6,15.35 U4.5@16.55,15.35 ; C40.1 17.25,12.2 17.645,12.595 18.145,12.595 C28.1 U3.11@19.25,12.6 ; U3.10@19.25,13.1 U3.11@19.25,12.6 ; U3.11 U3.11@19.25,12.6
  Signal Layer 3 w0.3: v1(15.1,15.3) 15.1,10.844 15.5,10.444 JMP2.2
VCOM_RX: Con1.4 U1.23 | length 24.9
  Top Layer w0.1: v1(4.85,18.75) 4.915,18.685 5.115,18.685 5.3,18.5 U1.23
  Signal Layer 3 w0.1: v1(7.8,5.4) 14.655,5.4 14.805,5.25 v1(14.9,5.25)
  Bottom Layer w0.1: v1(4.85,18.75) 5.25,18.35 5.25,14.3 7.8,11.75 v1(7.8,5.4) ; v1(14.9,5.25) 14.958,5.192 14.958,3.892 Con1.4@15.25,3.6
VCOM_TX: Con1.5 U1.22 | length 24.3
  Top Layer w0.1: v1(5.45,18.9) U1.22
  Signal Layer 3 w0.1: v1(8.25,5.85) 8.334,5.85 8.484,5.7 v1(16.1,5.7)
  Bottom Layer w0.1: v1(5.45,18.9) 5.5,18.85 5.5,14.45 8.05,11.9 8.05,6.084 8.25,5.884 v1(8.25,5.85) ; v1(16.1,5.7) 16.55,6.15 Con1.5@16.55,7
VDAC: C31.1 C32.1 C33.1 JMP3.2 R10.1 R11.1 R12.1 U5.1 | length 20
  Top Layer w0.2: R12.1 23.3,19.2 23.3,23.1 R10.1@23.2,23.2 ; R10.1 23.3,23.45 23.3,24 R11.1@23.2,24.1
  Top Layer w0.3: C31.1 C31.1@15.5,21.15 ; JMP3.2 15.84,19.625 15.5,19.965 C31.1@15.5,21.15 ; C32.1@16.25,21.15 C31.1@15.5,21.15 ; C32.1 16.35,21.25 16.45,21.15 C33.1 17.165,21.15 18.415,19.9 18.74,19.9 18.75,19.89 U5.1 ; v2(22.3,18.25) 22.538,18.338 22.95,18.75 22.95,18.85 R12.1
  Signal Layer 3 w0.3: JMP3.2 16.89,18.25 v2(22.3,18.25)
VDCDC: C8.1 C11.1 L2.1 L3.1 L4.2 TPJ2.1 U1.28 | length 30.2
  Top Layer w0.1: v2(3.3,12.15) 3.8,12.65 4.341,12.65 4.641,12.95 TPJ2.1 4.696,12.796 4.696,12.246 v2(4.6,12.15)
  Top Layer w0.2: v2(3.6,23.15) L3.1 ; C11.1 7.665,16.5 7.72,16.555 7.72,16.57 7.9,16.75 U1.28 ; v2(11.25,24) 11.327,24.077 11.327,24.202 L2.1@11.75,24.625
  Signal Layer 3 w0.2: v2(3.6,23.15) 4.7,23.15 5.7,24.15 10.992,24.15 11.142,24 v2(11.25,24)
  Signal Layer 3 w0.3: v2(3.3,12.15) 3.3,12.231 3.15,12.381 3.15,22.619 3.6,23.069 v2(3.6,23.15) ; v2(4.6,12.15) 4.6,13.778 7.193,16.371 7.271,16.371 v1(7.3,16.4)
VMCU: C9.1 C10.1 C12.1 C13.1 C14.1 C15.1 C17.1 C18.1 Con1.1 JMP1.1 JMP2.1 JMP3.1 U1.26 U1.29 U1.30 | length 37.3
  Top Layer w0.152: C12.1 8.05,14.9 8.05,16.2 8.274,16.424 8.349,16.424 C13.1@8.4,16.475 ; U1.29 8.3,16.562 8.35,16.512 C13.1@8.35,16.5 ; U1.30 8.7,16.85 8.859,16.691 8.859,16.578 8.937,16.5 C15.1@8.95,16.5 ; C15.1@8.9,16.449 C15.1@8.994,16.449 ; C15.1@9.048,16.452 9.4,16.1 C14.1
  Top Layer w0.2: C9.1 6.725,14.75 6.35,15.125 6.35,16.2 6.595,16.445 6.695,16.445 C10.1 6.765,16.5 6.82,16.555 6.82,16.72 7.1,17 U1.26
  Top Layer w0.5: JMP1.1 5.85,10.6 5.85,14.05 6.4,14.6 6.6,14.6 6.9,14.9 8.05,14.9 C12.1 ; C12.1@8.533,15 9.4,15 C14.1
  Top Layer w0.75: JMP1.1@5.95,10.65 11.85,10.65 11.925,10.575 12.585,10.575 JMP2.1
  Signal Layer 3 w0.3: JMP2.1 14.55,11.79 14.55,16.15 v2@14.5,16.2
  Bottom Layer w0.3: JMP3.1@13.9,19.05 13.9,17.05 14.5,16.45 v2@14.5,16.372
  Bottom Layer w0.75: JMP2.1@12.95,10.25 12.95,10.21 JMP2.1 13.335,9.825 13.375,9.825 14,9.2 Con1.1
  other v2: 14.55,16.2
VREF: C20.1 JMP1.2 U2.5 | length 10.2
  Top Layer w0.3: v2(2.5,18.35) 2.5,18.431 2.95,18.881 C20.1@2.95,18.927 ; C20.1 3.15,19.1 3.25,19.2 3.25,19.25 U2.5@3.25,20.175
  Signal Layer 3 w0.3: v2(2.5,18.35) 2.5,18.269 2.65,18.119 2.65,10.704 2.91,10.444 JMP1.2
Vref2ADC: R21.2 R22.2 | length 23.3
  Top Layer w0.1: R22.2 5.094,22.244 5.594,22.244 v1(5.65,22.3) ; R21.2 21.445,16.655 21.445,16.405 v1(21.45,16.4)
  Signal Layer 3 w0.1: v1(5.65,22.3) 6.45,21.5 10.6,21.5 11,21.9 v1(21.45,21.9)
  Bottom Layer w0.1: v1(21.45,16.4) v1(21.45,21.9)
pads on no net: Con1.6 Con1.9 Con1.10 U1.0@7.45,18.85 U1.0@7.45,20.15 U1.0@8.75,18.85 U1.0@8.75,20.15 U2.1 U2.2 U2.3 U2.6 U2.7 U4.1 U4.2 U4.3 U4.6 U4.7 U5.3 U5.9

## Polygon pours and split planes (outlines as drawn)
GND on Top Layer "GND_L01_P002" (solid, remove dead copper, pour order 2): 0,0 25,0 25,25.5 0,25.5
VDCDC on Top Layer "VDCDC_L01_P001" (solid, remove dead copper, pour order 1): 2.4,14.05 3,13.45 3,12.05 3.25,11.8 4.7,11.8 5.15,12.25 5.15,13.35 4.35,14.15 4.35,14.95 4.3,15 2.4,15
GND on Signal Layer 2 "GND_L02_P003" (solid, remove dead copper, pour order 3): 0,0 25,0 25,25.5 0,25.5
GND on Signal Layer 3 "GND_L03_P005" (solid, remove dead copper, pour order 5): 0,0 25,0 25,25.5 0,25.5
GND on Bottom Layer "GND_L04_P006" (solid, remove dead copper, pour order 6): 0,0 25,0 25,25.5 0,25.5

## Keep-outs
Top Layer:
  rectangle: 6.45,17.8 9.8,21.2
  region: 4.65,25.75 4.65,25 5.6,24.05 5.6,23.65 7.8,23.65 7.8,21.85 8.8,21.85 8.8,24.65 6.35,24.65 6.35,25.75

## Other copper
Top Layer:
  region net NetAT1_1: 5,25.5 6,25.5 6,24.3 5.7,24.3 5,25
  region net GND: 2.2,25.5 3.8,25.5 3.8,24.7 2.2,24.7

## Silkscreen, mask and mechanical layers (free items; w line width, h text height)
BOARD OUTLINE 1:
  the board outline again, w0.2
Mechanical 2:
  lines w0.1: -0.5,0 0.5,0 ; 0,-0.5 0,0.5
Top Overlay 1:
  text "CGM Board V2.0" at 0.5,27.1 h2.5
  text "WAKE" at 2.6,2.69 h1.2 r90
  text "RST" at 14.95,2.5 h1.2 r90
Bottom Overlay 1:
  region: 5.143,28.939 5.143,28.843 5.304,28.843 5.304,28.971 5.143,28.971
  region: 5.014,28.618 5.046,28.618 5.046,28.586 5.111,28.586 5.111,28.554 5.336,28.554 5.336,28.586 5.368,28.586 5.368,28.618 5.432,28.618 5.432,28.682 5.464,28.682 5.464,28.746 5.496,28.746 5.496,28.907 5.464,28.907 5.464,28.971 5.432,28.971 5.432,29.004 5.4,29.004 5.4,29.036 5.368,29.036 5.368,29.068 5.304,29.068 5.304,29.1 5.111,29.1 5.111,29.068 5.046,29.068 5.046,29.036 5.014,29.036 5.014,29.004 4.982,29.004 4.982,28.939 4.95,28.939 4.95,28.714 4.982,28.714 4.982,28.65 5.014,28.65 hole: 5.304,28.65 5.304,28.811 5.207,28.811 5.207,28.779 5.175,28.779 5.175,28.714 5.143,28.714 5.143,28.682 5.111,28.682 5.111,28.65 5.079,28.65 5.079,28.714 5.111,28.714 5.111,28.779 5.143,28.779 5.143,28.811 5.111,28.811 5.111,28.843 5.079,28.843 5.079,28.971 5.111,28.971 5.111,29.004 5.368,29.004 5.368,28.65 5.336,28.65
  region: 8.261,21.9 8.582,21.9 8.582,22.029 8.55,22.029 8.55,22.125 8.518,22.125 8.518,22.254 8.486,22.254 8.486,22.382 8.454,22.382 8.454,22.479 8.421,22.479 8.421,22.575 8.389,22.575 8.389,22.511 8.357,22.511 8.357,22.382 8.325,22.382 8.325,22.254 8.293,22.254 8.293,22.157 8.261,22.157 8.261,22.029 8.229,22.029 8.229,21.9
  region: 6.621,21.514 7.071,21.514 7.071,21.996 7.039,21.996 7.039,22.029 6.557,22.029 6.557,21.514 6.589,21.514
  region: 6.654,22.768 6.557,22.768 6.557,22.286 7.071,22.286 7.071,22.768 6.686,22.768
  region: 14.464,22.286 14.464,22.768 13.95,22.768 13.95,21.514 14.464,21.514 14.464,22.254
  region: 7 vertices and 18 holes, not listed, extent 1.704,20.454 23.304,30.321
  text "Debug Connector" at 23.15,8.2 h1.2
Mechanical 26:
  lines w0.2: -125.405,-0.962 -120.405,-0.962 ; -125.393,46.038 -120.405,46.038 ; -117.901,-72.299 -112.901,-72.299 ; -54.197,-94.993 -54.197,-89.993 ; -54.197,90.007 -54.197,95.007 ; 17.103,-94.993 17.103,-89.993 ; 17.103,90.007 17.103,95.007 ; 88.303,-94.993 88.303,-89.993 ; 88.303,90.007 88.303,95.007 ; 154.595,-47.962 159.595,-47.962 ; 154.595,-0.962 159.595,-0.962 ; 154.595,46.038 159.583,46.038 ; -125.393,-94.993 -125.393,94.999 159.595,94.999 159.595,-94.993 -125.393,-94.993 ; -120.405,-89.993 -120.405,90.007 154.595,90.007 154.595,-89.993 -120.405,-89.993
  text "1" at -92.505,91.578 h1.52
  text "2" at -20.197,91.578 h1.52
  text "3" at 52.403,91.578 h1.52
  text "4" at 123.203,91.578 h1.52
  text "D" at 156.593,72.438 h1.52
  text "D" at -123.518,71.233 h1.52
  text "C" at -123.518,23.738 h1.52
  text "C" at 156.466,23.738 h1.52
  text "A" at -146.017,5.201 h1.52
  text "B" at -123.518,-23.862 h1.52
  text "B" at 156.466,-23.862 h1.52
  text "A" at 156.466,-71.362 h1.52
  text "1" at -91.285,-93.435 h1.52
  text "2" at -20.197,-93.435 h1.52
  text "3" at 52.103,-93.435 h1.52
  text "4" at 122.803,-93.435 h1.52
Mechanical 27:
  circle w0.152: c70.608,-82.839 r1.778
  circle w0.152: c70.608,-82.839 r0.762
  lines w0.152: 59.609,-82.839 66.975,-82.839 ; 68.322,-82.839 72.894,-82.839 ; 60.371,-83.601 60.371,-82.077 66.213,-81.061 66.188,-84.617 60.371,-83.601
  lines w0.2: 34.575,-89.95 34.575,-77.425 ; 34.575,-77.369 74.589,-77.369 ; 34.589,-86.369 74.589,-86.369 ; 54.869,-86.322 54.869,-77.407 ; 134.589,-89.98 134.589,-86.369 ; 144.589,-86.369 144.589,-77.369 ; 154.589,-86.369 74.589,-86.369 ; 154.589,-77.369 74.589,-77.369 ; 74.589,-86.369 74.589,-77.369
  text "SIZE" at 36.589,-79.369 h1.52
  text "DOC NO" at 76.589,-79.369 h1.52
  text "REV" at 146.589,-79.369 h1.52
  text "PROJECTION" at 55.885,-79.718 h1.52
  text ".BoardRevision" at 146.309,-84.29 h2.54
  text "A4" at 39.239,-84.744 h2.54
  text ".BoardName" at 79.088,-84.744 h2.54
  text "REF" at 36.589,-88.369 h1.52
  text "SHEET" at 135.589,-88.369 h1.52
  text "1 of 2" at 145.43,-89.406 h1.52
Mechanical 28:
  lines w0.2: -125.404,-0.963 -120.404,-0.963 ; -125.392,46.037 -120.404,46.037 ; -117.9,-72.3 -112.9,-72.3 ; 154.596,-47.963 159.596,-47.963 ; 154.596,46.037 159.596,46.037
  lines w0.203: -120.429,-89.995 -120.429,90.005 ; -120.404,-89.995 154.596,-89.995 154.596,90.005 -120.404,90.005 ; -54.196,-94.995 -54.196,-89.995 ; -54.196,90.005 -54.196,95.005 ; 17.104,-94.995 17.104,-89.995 ; 17.104,90.005 17.104,95.005 ; 88.304,-94.995 88.304,-89.995 ; 88.304,90.005 88.304,95.005 ; -125.392,-94.995 -125.392,94.997 159.596,94.997 159.596,-94.995 -125.392,-94.995
  text "4" at -91.487,91.577 h1.52
  text "3" at -19.18,91.577 h1.52
  text "2" at 53.42,91.577 h1.52
  text "1" at 124.22,91.577 h1.52
  text "D" at 157.61,72.437 h1.52
  text "D" at -122.501,71.232 h1.52
  text "C" at -122.501,23.737 h1.52
  text "C" at 157.111,19.687 h1.52
  text "A" at -145,5.2 h1.52
  text "B" at -122.501,-23.863 h1.52
  text "B" at 157.61,-24.963 h1.52
  text "A" at 156.592,-71.287 h1.52
  text "A" at 157.483,-71.363 h1.52
  text "4" at -90.268,-93.437 h1.52
  text "3" at -19.18,-93.437 h1.52
  text "2" at 52.967,-93.437 h1.52
  text "1" at 123.82,-93.437 h1.52
Mechanical 29:
  circle w0.152: c-97.515,-87.365 r1.778
  circle w0.152: c-97.515,-87.365 r0.762
  lines w0.152: -99.801,-87.365 -95.229,-87.365 ; -93.121,-85.587 -93.096,-89.143 ; -32.794,-82.828 -25.428,-82.828 ; -32.032,-81.05 -26.19,-82.066 -26.19,-83.59 -32.006,-84.606
  lines w0.2: -132.906,-9.795 -132.906,-0.795 ; -120.407,-86.359 -40.407,-86.359 -0.407,-86.359 ; -120.407,-77.359 -40.407,-77.359 -0.407,-77.359 ; -101.496,-90.895 -101.496,-81.895 ; -100.407,-89.969 -100.407,-86.359 ; -20.687,-86.311 -20.687,-77.396 ; -0.393,-89.518 -0.393,-77.4
  text "REV" at -134.906,-2.795 h1.52
  text "SHEET" at -93.903,-73.154 h1.52
  text "2 of 2" at -103.591,-74.127 h1.52
  text "SIZE" at -2.407,-79.359 h1.52
  text "PROJECTION" at -21.703,-79.707 h1.52
  text "DOC NO" at -103.496,-83.895 h1.52
  text ".BoardRevision" at -112.127,-84.279 h2.54
  text "A4" at -5.057,-84.733 h2.54
  text "REF" at -2.407,-88.359 h1.52
  text ".BoardName" at -105.996,-89.27 h2.54
Mechanical 30:
  lines w0.2: 34.575,-77.369 34.575,-56.53 154.575,-56.53 ; 34.575,-73.434 74.575,-73.434 ; 34.575,-69.434 74.575,-69.434 ; 34.575,-65.434 74.575,-65.434 ; 74.575,-69.435 154.575,-69.435 ; 74.575,-61.434 154.575,-61.434 ; 74.581,-77.369 74.581,-56.53 ; 74.581,-56.519 74.581,-51.3 154.625,-51.3
  text "BRD4183A: EFR32xG22 QFN32 2.4 GHz 6 dBm" at 75.675,-54.575 h1.8
  text "CUSTOMER" at 75.683,-58.446 h1.27
  text "PROJECT NO" at 36.059,-59.462 h1.52
  text "SILICON LABS" at 93.125,-60.3 h2.5
  text "DRAWING TITLE" at 75.912,-63.374 h1.52
  text "BRD4183" at 36,-64.3 h2.1
  text "DATE" at 36.059,-67.59 h1.52
  text "EFR32xG22 QFN32 2.4 GHz 6 dBm Radio Board" at 75.825,-67.625 h1.8
  text "'.Print_Date'" at 54.347,-68.606 h1.52
  text "SHEET NAME" at 75.709,-71.527 h1.52
  text "DRAWN" at 36.059,-71.654 h1.52
  text "CHECK" at 36.059,-75.718 h1.52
